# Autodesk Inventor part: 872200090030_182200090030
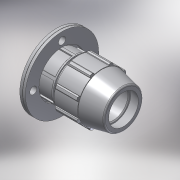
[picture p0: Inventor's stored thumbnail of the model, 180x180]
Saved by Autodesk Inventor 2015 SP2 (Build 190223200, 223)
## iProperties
Created: 2017-02
Part Number: 872200090030_182200090030
Material: PVC-Piping
Description: PLASSON COMPRESSION FLANGE ADAPTOR 90-3"
Document SubType Name: Modeling
Designer: KIM
Mass: 92.6774 g
Surface Area: 199.44 cm^2
Volume: 66.1981 cm^3
Density: 1.4 g/cm^3
Appearance: Smooth - White
Author: KIM
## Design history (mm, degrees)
derived "87220.ipt"
feature "Solid1::87220.ipt"
tag "TaggingFeature1"
body "Solid1"
other parameters: "d4" = 27.71429, "d5" = 62.08, "d7" = 152, "d9" = 27.71429, "d11" = 5.54286, "d12" = 121.6, "d13" = 120 deg, "d14" = 117, "d15" = 12 deg, "d18" = 4.5, "d19" = 35 deg, "d20" = 17.5 deg, "d21" = 141.36, "d23" = 0, "d25" = 360 deg, "d27" = 3.04, "d34" = 7.6, "d36" = 0, "d42" = 67.9, "d43" = 4.56, "d46" = 2.7, "d53" = 1.8, "d55" = 360 deg, "d70" = 194, "d73" = 16.16667, "d74" = 90 deg, "d75" = 0.3, "d77" = 18, "d80" = 0, "d82" = 360 deg, "d85" = 129.2, "d86" = 121.6, "d87" = 2.5, "d88" = 0.3, "d93" = 9.7, "d94" = 182, "E_" = 152, "H_" = 194, "l_" = 182, "S_" = 18
